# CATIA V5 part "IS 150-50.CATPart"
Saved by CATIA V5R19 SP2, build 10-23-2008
Part number: IS 150-50
Bounding box of the stored display mesh (mm): x -15.868 to 15.868, y -15.868 to 15.868, z 0 to 150
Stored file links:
  C:\Users\Bora\Desktop\3D Katı model\IS serisi\IS 150\IS 150-50.CATPart
  C:\Program Files\Dassault Systemes\B19\intel_a\reffiles\standard\MetricThickPitch.txt
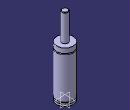
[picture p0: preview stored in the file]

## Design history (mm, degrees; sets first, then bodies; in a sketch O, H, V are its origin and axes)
Body1 (main body)
  Sketch1 on yz-plane, origin (0, 0, 0), H (0, 1, 0), V (0, 0, 1)
    point P3 (6, 149)
    point P5 (6, 149)
    point P7 (16, 88.5)
    point P8 (16, 86.5)
    point P12 (16, 86.5)
    point P13 (16, 88.5)
    line L1 (16, 0) -> (16, 4)
    line L2 (6, 149) -> (6, 98)
    arc A1 centre (5, 149) radius 1 from (6, 149) to (5, 150) ccw
    arc A2 centre (16, 87.5) radius 1 from (16, 88.5) to (16, 86.5) ccw
    line L3 (13.5, 7.5) -> (13.5, 4)
    line L4 (16, 7.5) -> (16, 86.5)
    line L5 (16, 88.5) -> (16, 98)
    line L6 (0, 0) -> (16, 0)
    line L7 (13.5, 4) -> (16, 4)
    line L8 (13.5, 7.5) -> (16, 7.5)
    line L9 (6, 98) -> (16, 98)
    line L10 (5, 150) -> (0, 150)
    point P15 (0, 150)
    horizontal: L6 H, L7 H, L8 H, L9 H
    tangency: L10 A1
    coincidence: P15 V, P3 P5, P7 P13, P8 P12
  Shaft1: profile Sketch1, axis Sketch1.V, angle 360
  Sketch2 on face of Shaft1 from Sketch1.L6, origin (0, 0, 0), H (1, 0, 0), V (0, -1, 0)
    point P1 (0, 0)
  Hole1: placed by Sketch2, at (0, 0, 0) direction (0, 0, 1), diameter 6.647, depth 7, threaded "M8", thread diameter 8, thread depth 7, pitch 1.25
